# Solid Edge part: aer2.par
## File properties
Author: Argo
Template: Normal.par
Last saved by: haldur
Revision: 16
Application: Solid Edge
Material: Wood, Birch
Face Style: Tan
Fill Style: Cork
Virtual Style: Polished paper birch
Coef. of Thermal Exp: 0.0
Thermal Conductivity: 0.0
Specific Heat: 0.0
Modulus of Elasticity: 0.0
Poission's Ratio: 0.0
Yield Stress: 0.0
Ultimate Stress: 0.0
Elongation: 0.0
Density: 711,000 kg/m^3
Accuracy: 0,99
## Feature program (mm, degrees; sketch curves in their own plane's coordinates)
sketch for "unnamed Protrusion 1" plane through (0, 0, 0) normal (0, -1, 0) x-axis (1, 0, 0)
  line (-32.5685, 46.8663) -> (-32.5685, -18.5848)
  line (-32.5685, -18.5848) -> (-30.06, -29.2303)
  line (-30.06, -29.2303) -> (-30.06, -37.7303)
  arc centre (-33.56, -37.7303) radius 3.5 from (-30.06, -37.7303) to (-33.56, -41.2303) cw
  line (-33.56, -41.2303) -> (-37.56, -41.2303)
  arc centre (-37.56, -37.7303) radius 3.5 from (-37.56, -41.2303) to (-41.06, -37.7303) cw
  line (-41.06, -37.7303) -> (-41.06, -29.47)
  arc centre (-39.56, -29.47) radius 1.5 from (-41.06, -29.47) to (-40.9853, -29.0025) cw
  line (-40.9853, -29.0025) -> (-37.5685, -18.5848)
  line (-37.5685, 46.8663) -> (-37.5685, -18.5848)
  line (-37.5685, 46.8663) -> (-37.5685, 59.8663)
  line (-37.5685, 59.8663) -> (-37.5685, 77.8663)
  arc centre (-35.5685, 77.8663) radius 2 from (-37.5685, 77.8663) to (-35.5685, 79.8663) cw
  line (-35.5685, 79.8663) -> (-34.5685, 79.8663)
  arc centre (-34.5685, 77.8663) radius 2 from (-34.5685, 79.8663) to (-32.5685, 77.8663) cw
  line (-32.5685, 77.8663) -> (-32.5685, 59.8663)
  line (-32.5685, 59.8663) -> (-32.5685, 46.8663)
extrude "unnamed Protrusion 1" add finite 3 along -normal
fillet "Round_1" radius 1
fillet "Round_2" radius 1
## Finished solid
Body 1: solid body, 41 faces, 91 edges, 52 vertices.
  Faces by surface: cylinder 21, plane 10, torus 10
  Edges by curve: line 45, circle 40, ellipse 6
Bounding box of the edges (mm; curved faces can reach further): 11.000 x 3.000 x 121.097, from (-41.06, 0, -41.2303) to (-30.06, 3, 79.8663).
Cylindrical faces by radius (mm): R1 x16, R1.5 x1, R2 x2, R3.5 x2
Toroidal faces (ring radius, tube radius in mm): R0.5 r1 x2, R1 r1 x4, R2.5 r1 x4
Planar faces by outward normal: +x 2, +y 1, +z 1, -x 2, -y 1, -z 1, oblique 2
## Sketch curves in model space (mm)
arc centre (-33.56, 0, -37.7303) radius 3.5 from (-30.06, 0, -37.7303) through (-31.1582, 0, -40.2761) to (-33.56, 0, -41.2303)
line (-33.56, 0, -41.2303) -> (-37.56, 0, -41.2303)
arc centre (-37.56, 0, -37.7303) radius 3.5 from (-37.56, 0, -41.2303) through (-40.1058, 0, -40.1321) to (-41.06, 0, -37.7303)
line (-41.06, 0, -37.7303) -> (-41.06, 0, -29.47)
arc centre (-39.56, 0, -29.47) radius 1.5 from (-41.06, 0, -29.47) through (-41.0412, 0, -29.2333) to (-40.9853, 0, -29.0025)
line (-40.9853, 0, -29.0025) -> (-37.5685, 0, -18.5848)
line (-37.5685, 0, 46.8663) -> (-37.5685, 0, -18.5848)
line (-37.5685, 0, 46.8663) -> (-37.5685, 0, 59.8663)
line (-37.5685, 0, 59.8663) -> (-37.5685, 0, 77.8663)
arc centre (-35.5685, 0, 77.8663) radius 2 from (-37.5685, 0, 77.8663) through (-36.941, 0, 79.321) to (-35.5685, 0, 79.8663)
line (-35.5685, 0, 79.8663) -> (-34.5685, 0, 79.8663)
arc centre (-34.5685, 0, 77.8663) radius 2 from (-34.5685, 0, 79.8663) through (-33.1138, 0, 79.2387) to (-32.5685, 0, 77.8663)
line (-32.5685, 0, 77.8663) -> (-32.5685, 0, 59.8663)
line (-32.5685, 0, 59.8663) -> (-32.5685, 0, 46.8663)
line (-32.5685, 0, 46.8663) -> (-32.5685, 0, -18.5848)
line (-32.5685, 0, -18.5848) -> (-30.06, 0, -29.2303)
line (-30.06, 0, -29.2303) -> (-30.06, 0, -37.7303)
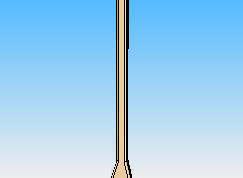
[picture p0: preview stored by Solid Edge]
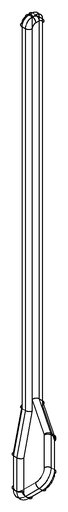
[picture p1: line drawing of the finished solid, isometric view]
